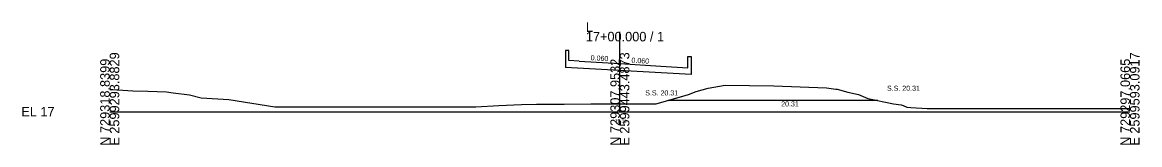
# Model space of a CAD drawing. Extents: x -26 to 3303, y -10 to 9555.
# Drawn here: x 974.3 to 1302.8, y 3990.3 to 4026.3 of the extents above; entities that cross this region are included whole.
import ezdxf

# ---------------------------------------------------------------- set-up
doc = ezdxf.new("R2010")
doc.units = 0
for name, color, linetype in [('Exist Cross Section Cell', 7, 'Continuous'), ('Exist XS Center Line Elevation Label', 7, 'Continuous'), ('Exist XS Ground Line', 7, 'Continuous'), ('Prop XS Bridge', 7, 'Continuous'), ('Prop XS Ditch Standard Text', 7, 'Continuous'), ('Prop XS Dump Level', 7, 'Continuous'), ('Prop XS Earthwork Shape', 7, 'Continuous'), ('Prop XS Finish Grade Earthwork', 7, 'Continuous'), ('Prop XS SE Text', 7, 'Continuous'), ('Prop XS SS Elevation Text', 7, 'Continuous')]:
    doc.layers.add(name, color=color, linetype=linetype)

msp = doc.modelspace()

# ---------------------------------------------------------------- linework, layer by layer
at = {"layer": 'Exist Cross Section Cell'}
for p, q in [((1150, 4000), (1150, 4023.51)), ((1000, 4000), (1150, 4000)), ((1150, 4000), (1300, 4000))]:
    msp.add_line(p, q, dxfattribs=at)
at = {"layer": 'Exist XS Ground Line'}
for points in [[(1000, 4006.58), (1000.93, 4006.54), (1006.77, 4006.17), (1011.24, 4006.02), (1016.67, 4005.84), (1018.67, 4005.6), (1023.43, 4005.02), (1026.87, 4004.12), (1035.05, 4003.61), (1048.57, 4001.47), (1057.3, 4001.47), (1059.5, 4001.47), (1061.47, 4001.47), (1080.22, 4001.47), (1090.61, 4001.47), (1095.73, 4001.47), (1098.67, 4001.47), (1107.68, 4001.47), (1114.38, 4001.83), (1121.1, 4002.15), (1125.51, 4002.2), (1133.64, 4002.25), (1141.43, 4002.3), (1145.01, 4002.32), (1150, 4002.31), (1159.58, 4002.31), (1160.72, 4002.32), (1163.71, 4003.18), (1170.17, 4005.12), (1172.44, 4005.97), (1175.98, 4006.89), (1180.96, 4007.84), (1195.27, 4007.6), (1210.79, 4007.05), (1213.5, 4006.66), (1213.94, 4006.65), (1217.07, 4005.77), (1220.17, 4005.03), (1222.88, 4003.92), (1230.46, 4002.35), (1232.68, 4002.04), (1233.26, 4001.88), (1234.42, 4001.37)], [(1234.42, 4001.37), (1235.56, 4001.29), (1240.38, 4001), (1248.04, 4001), (1267.86, 4001), (1278.98, 4001), (1284.43, 4001), (1289, 4001), (1292.98, 4001), (1297.54, 4001), (1298.35, 4001), (1300, 4001)]]:
    msp.add_lwpolyline(points, dxfattribs=at)
at = {"layer": 'Prop XS Bridge'}
for p, q in [((1134, 4018.05), (1134, 4015.05)), ((1135, 4018.05), (1134, 4018.05)), ((1135, 4015.05), (1135, 4018.05)), ((1134, 4015.05), (1134, 4013.05)), ((1138, 4014.87), (1135, 4015.05)), ((1138, 4014.87), (1150, 4014.15)), ((1170, 4012.95), (1170, 4016.25)), ((1170, 4016.25), (1171, 4016.25)), ((1171, 4016.25), (1171, 4013.25)), ((1171, 4010.97), (1134, 4013.05)), ((1150, 4014.15), (1162, 4013.43)), ((1162, 4013.43), (1170, 4012.95)), ((1171, 4013.25), (1171, 4010.97))]:
    msp.add_line(p, q, dxfattribs=at)
at = {"layer": 'Prop XS Dump Level'}
for p, q in [((1138, 4014.87), (1150, 4014.15)), ((1150, 4014.15), (1162, 4013.43))]:
    msp.add_line(p, q, dxfattribs=at)
at = {"layer": 'Prop XS Earthwork Shape'}
for points in [[(1220.17, 4005.03), (1222.88, 4003.92), (1225.81, 4003.31), (1225.8, 4003.31), (1164.16, 4003.31), (1170.17, 4005.12), (1172.44, 4005.97), (1175.98, 4006.89), (1180.96, 4007.84), (1195.27, 4007.6), (1210.79, 4007.05), (1213.5, 4006.66), (1213.94, 4006.65), (1217.07, 4005.77)], [(1225.81, 4003.31), (1225.8, 4003.31), (1164.16, 4003.31), (1170.17, 4005.12), (1172.44, 4005.97), (1175.98, 4006.89), (1180.96, 4007.84), (1195.27, 4007.6), (1210.79, 4007.05), (1213.5, 4006.66), (1213.94, 4006.65), (1217.07, 4005.77), (1220.17, 4005.03), (1222.88, 4003.92)]]:
    msp.add_lwpolyline(points, close=True, dxfattribs=at)
at = {"layer": 'Prop XS Finish Grade Earthwork'}
for p, q in [((1225.8, 4003.31), (1164.16, 4003.31)), ((1225.81, 4003.31), (1225.8, 4003.31))]:
    msp.add_line(p, q, dxfattribs=at)

# ---------------------------------------------------------------- texts
at = {"layer": 'Exist Cross Section Cell'}
for s, p in [('L', (1140, 4023.51)), ('17+00.000 / 1', (1140, 4020.71)), ('EL 17', (974, 3998.6))]:
    msp.add_text(s, height=2.8, dxfattribs=at).set_placement(p)
for s, p in [('N 729318.8399', (1000, 3990)), ('E 2599293.8829', (1002.8, 3990)), ('N 729307.9532', (1150, 3990)), ('E 2599443.4873', (1152.8, 3990)), ('N 729297.0665', (1300, 3990)), ('E 2599593.0917', (1302.8, 3990))]:
    msp.add_text(s, height=2.8, rotation=90, dxfattribs=at).set_placement(p)
at = {"layer": 'Exist XS Center Line Elevation Label'}
msp.add_text('19.31', height=1, dxfattribs=at).set_placement((1148.55, 3996.81))
at = {"layer": 'Prop XS Ditch Standard Text'}
msp.add_text('20.31', height=1.5, dxfattribs=at).set_placement((1197.43, 4001.56))
at = {"layer": 'Prop XS SE Text'}
for p in [(1141.38, 4015.17), (1153.38, 4014.45)]:
    msp.add_text('0.060', height=1.5, rotation=356.5664, dxfattribs=at).set_placement(p)
at = {"layer": 'Prop XS SS Elevation Text'}
for p in [(1157.47, 4004.8), (1228.56, 4006.16)]:
    msp.add_text('S.S. 20.31', height=1.5, dxfattribs=at).set_placement(p)

doc.saveas('drawing.dxf')
